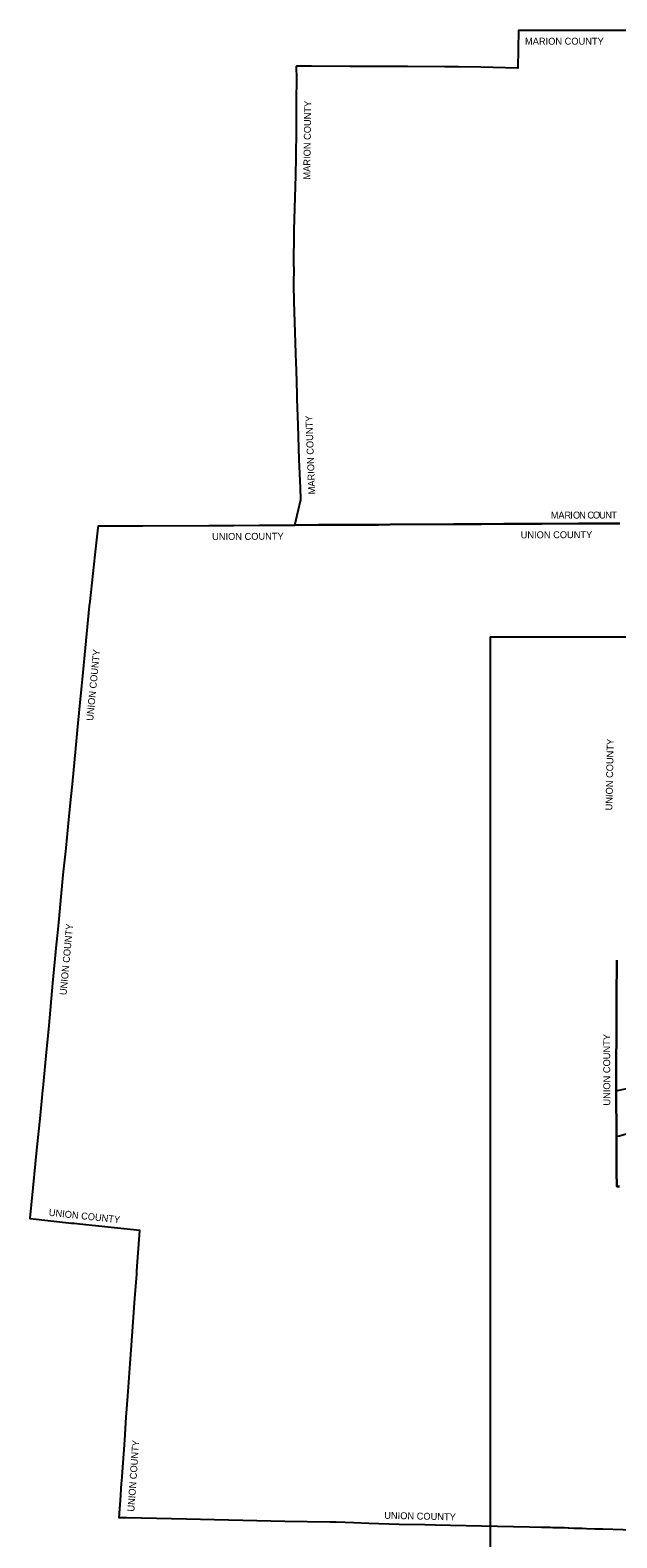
# Model space of a CAD drawing. Extents: x 1674899 to 2057726, y 653888 to 988278.
# Drawn here: x 1674899 to 1759512, y 767682 to 985196 of the extents above; entities that cross this region are included whole.
import ezdxf

# ---------------------------------------------------------------- set-up
doc = ezdxf.new("R2010")
doc.units = 0
for name, color, linetype in [('GM_X_Adjacent_County', 7, 'Continuous'), ('GM_X_Adjacent_County_Text', 7, 'Continuous'), ('GM_X_County', 7, 'Continuous'), ('GM_X_County_Road', 7, 'Continuous'), ('GM_X_Township', 7, 'Continuous'), ('GM_X_US_Route', 7, 'Continuous'), ('SH_Data', 7, 'Continuous'), ('SH_Named_Boundary', 7, 'Continuous')]:
    doc.layers.add(name, color=color, linetype=linetype)

msp = doc.modelspace()

# ---------------------------------------------------------------- linework, layer by layer
at = {"layer": 'GM_X_Adjacent_County'}
for points in [[(1759934, 914025), (1758493, 914019), (1753982, 914000), (1748682, 913976), (1743227, 913952), (1739940, 913938), (1735953, 913922), (1726840, 913858), (1725148, 913846), (1723205, 913838), (1716496, 913811), (1713053, 913797), (1713951, 917499), (1713884, 919153), (1713717, 923273), (1713542, 928222), (1713413, 931984), (1713394, 932362), (1713390, 932646), (1713295, 936133), (1713292, 936228), (1713269, 937144), (1713220, 938591), (1712975, 946055), (1712947, 948385), (1712954, 951015), (1712951, 951091), (1712992, 956331), (1713199, 964236), (1713260, 966868), (1713314, 970824), (1713332, 974830), (1713341, 978483), (1713329, 979699), (1713331, 979987), (1713338, 980070), (1715490, 980056), (1721062, 980018), (1724025, 979998), (1729335, 979998), (1734689, 979969), (1736696, 979953), (1739915, 979890), (1745248, 979765), (1745298, 979764), (1745299, 979824), (1745336, 982402), (1745376, 985192), (1746957, 985196), (1756190, 985192), (1761103, 985171)], [(1763343, 768740), (1757498, 768922), (1756522, 768952), (1756324, 768958), (1755133, 768994), (1754532, 769012), (1754174, 769024), (1753825, 769034), (1753509, 769044), (1753314, 769050), (1752609, 769080), (1752470, 769078), (1751954, 769119), (1751445, 769108), (1750802, 769126), (1750771, 769127), (1750298, 769142), (1749911, 769154), (1748977, 769182), (1748633, 769193), (1746906, 769210), (1739974, 769370), (1733297, 769524), (1731814, 769558), (1728095, 769617), (1723752, 769769), (1721603, 769842), (1719047, 769928), (1719010, 769929), (1718897, 769931), (1718838, 769932), (1718098, 769944), (1711635, 770051), (1697436, 770362), (1690970, 770502), (1688794, 770548), (1687754, 770588), (1687972, 773803), (1688036, 774749), (1688090, 775547), (1688110, 775836), (1688158, 776519), (1688534, 781789), (1688769, 785094), (1688986, 788144), (1689326, 792827), (1689614, 796784), (1690016, 802272), (1690262, 805669), (1690301, 806205), (1690722, 812023), (1682012, 812933), (1681252, 813012), (1680866, 813052), (1674899, 813685), (1674917, 813860), (1675148, 816210), (1675883, 823613), (1676368, 828621), (1676732, 832273), (1676760, 832584), (1676808, 833067), (1677110, 836191), (1677306, 838247), (1677531, 840609), (1677620, 841578), (1678185, 847722), (1678709, 853232), (1678835, 854552), (1679011, 856444), (1679673, 863327), (1680034, 866730), (1680177, 868186), (1680485, 871312), (1680811, 874619), (1680988, 876427), (1681487, 881540), (1681748, 884227), (1682085, 887713), (1682226, 889127), (1682370, 890581), (1682565, 892542), (1682900, 896063), (1683481, 902151), (1683546, 902749), (1684285, 909495), (1684713, 913407), (1684743, 913679), (1684770, 913678), (1690379, 913673), (1691130, 913677), (1700650, 913725), (1704212, 913742), (1707999, 913760), (1713053, 913797), (1716496, 913811), (1723205, 913838), (1725148, 913846), (1726840, 913858), (1735953, 913922), (1739940, 913938), (1743227, 913952), (1748682, 913976), (1753982, 914000), (1758493, 914019), (1759934, 914025)], [(1759514, 851039), (1759505, 848913), (1759489, 848768), (1759463, 847793), (1759463, 844341), (1759416, 832152), (1759482, 825563), (1759475, 820549), (1759498, 818358), (1759879, 818354)]]:
    msp.add_lwpolyline(points, dxfattribs=at)
at = {"layer": 'GM_X_County'}
msp.add_lwpolyline([(1759879, 818354), (1759498, 818358), (1759475, 820549), (1759482, 825563), (1759416, 832152), (1759463, 844341), (1759463, 847793), (1759489, 848768), (1759505, 848913), (1759514, 851039)], dxfattribs=at)
at = {"layer": 'GM_X_County_Road'}
msp.add_lwpolyline([(1759416, 832152), (1761564, 832643), (1761642, 832660), (1764071, 832622), (1764156, 832620)], dxfattribs=at)
at = {"layer": 'GM_X_Township'}
msp.add_lwpolyline([(1759879, 818354), (1759498, 818358), (1759475, 820549), (1759482, 825563), (1759416, 832152), (1759463, 844341), (1759463, 847793), (1759489, 848768), (1759505, 848913), (1759514, 851039)], dxfattribs=at)
at = {"layer": 'GM_X_US_Route'}
msp.add_lwpolyline([(1759482, 825563), (1759881, 825677), (1762279, 826378), (1762950, 826573), (1763952, 826869), (1764213, 826942), (1764404, 826999), (1765076, 827196), (1765952, 827450), (1765996, 827463)], dxfattribs=at)
at = {"layer": 'SH_Data'}
msp.add_lwpolyline([(1759482, 825563), (1759881, 825677), (1762279, 826378), (1762950, 826573), (1763952, 826869), (1764213, 826942), (1764404, 826999), (1765076, 827196), (1765952, 827450), (1765996, 827463)], dxfattribs=at)
at = {"layer": 'SH_Named_Boundary'}
msp.add_lwpolyline([(1741253, 762626), (1916253, 762626), (1916253, 897626), (1741253, 897626)], close=True, dxfattribs=at)

# ---------------------------------------------------------------- texts
at = {"layer": 'GM_X_Adjacent_County_Text'}
for s, rotation, p in [('MARION COUNTY', 0.00001, (1746264, 983102)), ('MARION COUNTY', 89.19654, (1715283, 963633)), ('MARION COUNTY', 92.18698, (1716021, 918244)), ('I', 0.12753, (1752777, 914732)), ('O', 0.12505, (1753186, 914733)), ('N', 0.12505, (1754070, 914735)), ('C', 0.12591, (1755258, 914737)), ('O', 0.12589, (1756072, 914739)), ('U', 0.12647, (1756957, 914741)), ('N', 0.12505, (1757841, 914743)), ('T', 0.12471, (1758726, 914745)), ('M', 0.12477, (1749991, 914726)), ('A', 0.12647, (1751078, 914728)), ('R', 0.12405, (1751963, 914730)), ('UNION COUNTY', 0.2701, (1701141, 911641)), ('UNION COUNTY', 0.21599, (1745642, 911878)), ('UNION COUNTY', 84.43173, (1683981, 885513)), ('UNION COUNTY', 88.7699, (1758862, 872619)), ('UNION COUNTY', 84.62721, (1680133, 845944)), ('UNION COUNTY', 90.09308, (1758562, 830043)), ('UNION COUNTY', 354.00506, (1677548, 814154)), ('UNION COUNTY', 86.03534, (1689917, 771440)), ('UNION COUNTY', 358.706, (1725957, 770435))]:
    msp.add_text(s, height=1000, rotation=rotation, dxfattribs=at).set_placement(p)

doc.saveas('drawing.dxf')
